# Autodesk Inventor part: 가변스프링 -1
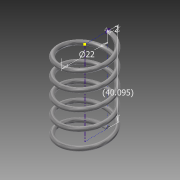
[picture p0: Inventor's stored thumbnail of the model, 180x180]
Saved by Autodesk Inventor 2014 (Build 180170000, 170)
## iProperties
Created: 2016-01
Part Number: 가변스프링 -1
Material: 스테인레스 스틸
Document SubType Name: Modeling
Designer: Administrator
Density: 8.08 g/cm^3
Appearance: 반연마
Mass: 8.67776 g
Surface Area: 21.7419 cm^2
Volume: 1.07398 cm^3
Author: Administrator
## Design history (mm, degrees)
sketch "스케치1"
  geometry: L1 (0, -40.095)-(11, -40.095); L2 (11, -40.095)-(11, 0); L3 (11, 0)-(0, 0); L4 (0, 0)-(0, -40.095); C1 r 1 at (11, 0); 1 further point
  constraints: 8 end point, 2 coincident, 2 parallel, 1 centre point, 1 horizontal, 1 perpendicular
  dimensions: "d0" = 2 diameter of C1; "d1" = 22 diameter of L2 L4; "d2" = 40.0955 distance of L1.end L2.end (derived)
feature "코일1" pitch "d3" = 10; turns "d5" = 5; dims "d4" = 40.0955 (= d2), "d6" = 0, angle "d7" = 90 deg, angle "d8" = 90 deg, "d9" = 0, "d10" = 0
sketch "스케치4"
  geometry: L1 (0, 10)-(0, 12) reference; 1 further point
  constraints: 1 vertical alignment
extrude "돌출3" cut sketch "스케치4" distance "d16" = 10; taper "d17" = 0 deg
node "작업 평면2"
sketch "스케치5"
  geometry: L1 (12, 0)-(10, 0) reference; 1 further point
  constraints: 1 horizontal alignment
extrude "돌출4" cut sketch "스케치5" distance "d19" = 10; taper "d20" = 0 deg
node "솔리드1"
node "절단 모서리 투영3"
node "절단 모서리 투영4"
other parameters: "d18" = 0
